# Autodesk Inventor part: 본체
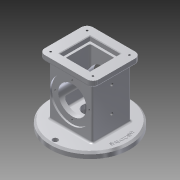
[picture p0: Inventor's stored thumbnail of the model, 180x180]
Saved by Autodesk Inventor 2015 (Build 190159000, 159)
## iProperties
Created: 2019-08
Part Number: 본체
Material: 알루미늄 6061
Document SubType Name: Modeling
Designer: now
Density: 2.7 g/cm^3
Appearance: 알루미늄 - 평지
Mass: 1038.06 g
Surface Area: 785.626 cm^2
Volume: 384.466 cm^3
Author: now
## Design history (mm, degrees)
sketch "스케치1"
  geometry: C1 r 67.5 at (0, 0); 1 further point
  constraints: 1 centre point, 1 coincident
  dimensions: "d0" = 135 diameter of C1
extrude "돌출1" new body sketch "스케치1" distance "d1" = 10; taper "d2" = 0 deg
chamfer "모따기1" distance "d3" = 3; stored, may be unused: second distance "d4" = 2, angle "d5" = 45 deg
sketch "스케치2"
  geometry: C1 r 64.5 at (0, 0) reference; 1 further point
  constraints: 1 horizontal alignment
  dimensions: "d6" = 59 distance of C1.centre point (-59, 0)
hole "구멍1" sketch "스케치2" at (-59, 0) diameter "d7" = 9; stored, may be unused: countersink angle "d11" = 90 deg, drill point angle "d13" = 118 deg; dims "d8" = 6, "d9" = 4, "d10" = 2, "d12" = 8
sketch "스케치4"
  geometry: L1 (37, 33)-(-37, 33); L2 (-37, 33)-(-37, -33); L3 (-37, -33)-(37, -33); L4 (37, -33)-(37, 33); L5 (37, 33)-(-37, -33); L6 (-37, 33)-(37, -33); C1 r 64.5 at (0, 0) reference
  constraints: 12 end point, 2 midpoint, 2 parallel, 1 horizontal, 1 perpendicular
  dimensions: "d23" = 66 distance of L3.end L1.start; "d24" = 74 distance of L1.start L1.end
extrude "돌출3" join sketch "스케치4" distance "d25" = 88; taper "d26" = 0 deg
sketch "스케치5"
  geometry: L1 (46, 41)-(-46, 41); L2 (-46, 41)-(-46, -41); L3 (-46, -41)-(46, -41); L4 (46, -41)-(46, 41); L5 (46, 41)-(-46, -41); L6 (-46, 41)-(46, -41); 1 further point
  constraints: 12 end point, 2 midpoint, 2 parallel, 1 horizontal, 1 perpendicular
  dimensions: "d27" = 82 distance of L3.end L1.start; "d28" = 92 distance of L1.start L1.end
extrude "돌출4" join sketch "스케치5" distance "d29" = 10; taper "d30" = 0 deg
fillet "모깎기1" dims "d31" = 10
fillet "모깎기2" dims "d32" = 3
fillet "모깎기3" dims "d33" = 3
fillet "모깎기4" dims "d34" = 3
fillet "모깎기5" dims "d35" = 3
sketch "스케치6"
  geometry: L1 (-33.5, -13)-(101.5, -13) reference; C1 r 24 at (34, 41); 1 further point
  constraints: 1 centre point, 1 vertical alignment
  dimensions: "d36" = 48 diameter of C1; "d37" = 54 distance from line of L1 C1.centre
extrude "돌출5" cut sketch "스케치6" stored distance "d38" = 10; taper "d39" = 0 deg
sketch "스케치7"
  geometry: C1 r 24 at (34, 41) reference; C2 r 35 at (34, 41); 1 further point
  constraints: 1 centre point, 1 coincident
  dimensions: "d40" = 70 diameter of C2
extrude "돌출6" cut sketch "스케치7" distance "d41" = 3; taper "d42" = 0 deg
sketch "스케치8"
  geometry: L1 (26, 26)-(-26, 26); L2 (-26, 26)-(-26, -26); L3 (-26, -26)-(26, -26); L4 (26, -26)-(26, 26); L5 (26, 26)-(-26, -26); L6 (-26, 26)-(26, -26); 1 further point
  constraints: 12 end point, 2 midpoint, 2 parallel, 1 horizontal, 1 perpendicular
  dimensions: "d43" = 52 distance of L1.end L2.end; "d44" = 52 distance of L1.start L1.end
extrude "돌출7" cut sketch "스케치8" distance "d45" = 8; taper "d46" = 0 deg
sketch "스케치9"
  geometry: L1 (22, -22)-(-22, -22); L2 (-22, -22)-(-22, 22); L3 (-22, 22)-(22, 22); L4 (22, 22)-(22, -22); L5 (22, -22)-(-22, 22); L6 (-22, -22)-(22, 22); 1 further point
  constraints: 12 end point, 2 midpoint, 2 parallel, 1 horizontal, 1 perpendicular
  dimensions: "d47" = 44 distance of L1.end L2.end; "d48" = 44 distance of L2.end L3.end
extrude "돌출8" cut sketch "스케치9" distance "d49" = 74; taper "d50" = 0 deg
sketch "스케치11"
  geometry: C1 r 67.5 at (0, 0) reference; C2 r 25 at (0, 0)
  constraints: 1 centre point, 1 coincident
  dimensions: "d51" = 50 diameter of C2
extrude "돌출9" cut sketch "스케치11" distance "d52" = 18; taper "d53" = 0 deg
sketch "스케치12"
  geometry: C1 r 25 at (0, 0) reference; C2 r 12.5 at (0, 0)
  constraints: 1 centre point, 1 coincident
  dimensions: "d54" = 25 diameter of C2
extrude "돌출10" cut sketch "스케치12" stored distance "d55" = 18; taper "d56" = 0 deg
fillet "모깎기6" dims "d57" = 3
fillet "모깎기7" dims "d58" = 3
fillet "모깎기8" dims "d59" = 3
sketch "스케치13"
  geometry: C1 r 24 at (0, 0) reference; 2 further points
  constraints: 1 vertical alignment
  dimensions: "d60" = 29 distance of C1.centre point (0, 29)
hole "구멍2" sketch "스케치13" at (0, 29) diameter "d61" = 3.242; stored, may be unused: countersink angle "d65" = 90 deg, drill point angle "d67" = 118 deg; dims "d62" = 4, "d63" = 4, "d64" = 2, "d66" = 6
sketch "스케치14"
  geometry: A1 r 10 centre (-36, -31) between (-46, -31) and (-36, -41) reference; A2 r 10 centre (36, -31) between (36, -41) and (46, -31) reference; A3 r 10 centre (36, 31) between (46, 31) and (36, 41) reference; A4 r 10 centre (-36, 31) between (-36, 41) and (-46, 31) reference; 1 further point
hole "구멍3" sketch "스케치14" at (-36, 31), (-36, -31), (36, -31), (36, 31) diameter "d71" = 3.242; stored, may be unused: countersink angle "d75" = 90 deg, drill point angle "d77" = 118 deg; dims "d72" = 4, "d73" = 4, "d74" = 2, "d76" = 6
sketch "스케치15"
  geometry: C1 r 64.5 at (0, 0) reference; C2 r 4.5 at (-59, 0) reference; 1 further point
  constraints: 1 coincident, 1 horizontal alignment, 2 other
feature "엠보싱1" sketch "스케치15" dims "d78" = 0.5, "d79" = 0
chamfer "모따기2" distance "d80" = 1; stored, may be unused: second distance "d81" = 2, angle "d82" = 45 deg
sketch "스케치16"
  geometry: L1 (13, -37.5)-(13, 97.5) reference; 3 further points
  constraints: 2 horizontal alignment
  dimensions: "d83" = 37 distance from line of L1 point (-24, 30); "d84" = 43 distance of point (-24, 30) point (-67, 30)
hole "구멍4" sketch "스케치16" at (-67, 30), (-24, 30) diameter "d85" = 4.917; stored, may be unused: countersink angle "d89" = 90 deg, drill point angle "d91" = 118 deg; dims "d86" = 12, "d87" = 4, "d88" = 2, "d90" = 15
node "솔리드1"
pattern_circular "원형 패턴1" dims angle "d15" = 90 deg
mirror "대칭1"
mirror "대칭2"
pattern_circular "원형 패턴2" dims angle "d69" = 360 deg
mirror "대칭3"
